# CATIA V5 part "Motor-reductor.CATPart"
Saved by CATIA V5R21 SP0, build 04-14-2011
Part number: Motor-reductor
Bounding box of the stored display mesh (mm): x 10 to 80, y -35 to 35, z -34.808 to 34.808
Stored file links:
  C:\Users\MIRCEA\Desktop\PRRO\CATIAV5\Motor-reductor.CATPart
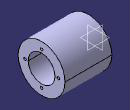
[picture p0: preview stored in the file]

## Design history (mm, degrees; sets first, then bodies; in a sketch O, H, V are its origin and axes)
Body1 (main body)
  Plane1: type Offset, RefPlane yz-plane, Offset 80
  Sketch1 on Plane1, origin (80, 0, 0), H (0, 1, 0), V (0, 0, 1)
    circle A1 centre (0, 0) radius 35
    circle A2 centre (0, 0) radius 20
    circle A3 centre (0, 25) radius 2
    circle A4 centre (25, 0) radius 2
    circle A5 centre (0, -25) radius 2
    circle A6 centre (-25, 0) radius 2
    radius A1 = 35
    radius A2 = 20
    radius A3 = 2
    radius A4 = 2
    radius A5 = 2
    radius A6 = 2
  Pad1: profile Sketch1, direction (-1, 0, 0), length 70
